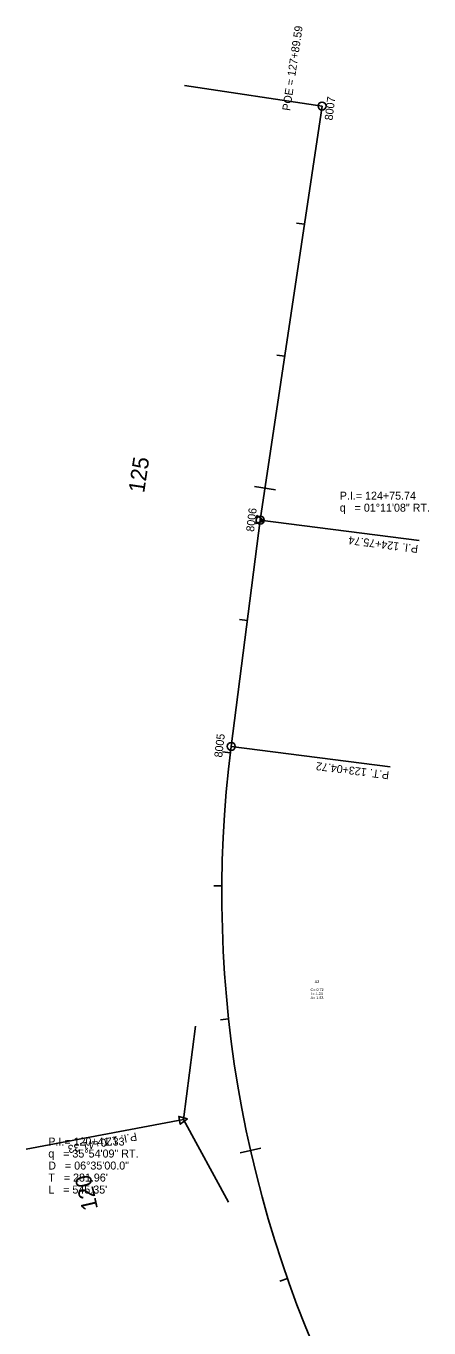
# Model space of a CAD drawing. Extents: x 1627557 to 1636561, y 783843 to 794002.
# Drawn here: x 1627557 to 1627859, y 785463 to 786439 of the extents above; entities that cross this region are included whole.
import ezdxf

# ---------------------------------------------------------------- set-up
doc = ezdxf.new("R2010")
doc.units = 0
for name, color, linetype in [('Point Numbers', 7, 'Continuous'), ('R_Drainage_Areas_Annot', 7, 'Continuous'), ('R_Horz Alg', 7, 'Continuous'), ('R_Horz Alg Annot', 7, 'Continuous')]:
    doc.layers.add(name, color=color, linetype=linetype)

msp = doc.modelspace()

# ---------------------------------------------------------------- linework, layer by layer
at = {"layer": 'R_Horz Alg'}
for p, q in [((1627732.9, 786068.26), (1627779.22, 786378.68)), ((1627711.17, 785898.63), (1627732.9, 786068.26))]:
    msp.add_line(p, q, dxfattribs=at)
for centre in [(1627779.22, 786378.68), (1627732.9, 786068.26), (1627711.17, 785898.63)]:
    msp.add_circle(centre, 3, dxfattribs=at)
msp.add_arc((1628574.42, 785788.02), 870.32, 172.69845, 208.60097, dxfattribs=at)
at = {"layer": 'R_Horz Alg Annot'}
for points in [[(1627779.22, 786378.68), (1627676.15, 786394.06)], [(1627760.06, 786290.95), (1627766, 786290.07)], [(1627745.31, 786192.05), (1627751.24, 786191.16)], [(1627728.57, 786093.44), (1627744.39, 786091.08)], [(1627732.9, 786068.26), (1627851.93, 786053.01)], [(1627717.32, 785993.9), (1627723.27, 785993.14)], [(1627711.17, 785898.63), (1627830.19, 785883.38)], [(1627704.62, 785894.68), (1627710.58, 785893.95)], [(1627698.13, 785794.25), (1627704.13, 785794.21)], [(1627703.19, 785693.75), (1627709.16, 785694.39)], [(1627709.07, 785557.06), (1627675.33, 785618.95), (1627684.29, 785688.87)], [(1627675.33, 785618.95), (1627557.4, 785596.78)], [(1627675.33, 785618.95), (1627557.4, 785596.78)], [(1627717.8, 785594.04), (1627733.4, 785597.58)], [(1627747.57, 785497.77), (1627753.23, 785499.76)]]:
    msp.add_lwpolyline(points, dxfattribs=at)
for points in [[(1627735.87, 786067.85), (1627729.52, 786065.71), (1627730.34, 786071.65)], [(1627678.28, 785619.51), (1627672.94, 785615.45), (1627671.83, 785621.35)]]:
    msp.add_lwpolyline(points, close=True, dxfattribs=at)

# ---------------------------------------------------------------- texts
at = {"layer": 'Point Numbers'}
for s, p in [('8007', (1627787.05, 786367.67)), ('8006', (1627728.2, 786059.31)), ('8005', (1627704.31, 785890.07))]:
    msp.add_text(s, height=6, rotation=83.28576, dxfattribs=at).set_placement(p)
at = {"layer": 'R_Drainage_Areas_Annot'}
for s, p in [('A2', (1627773.72, 785721.31)), ('C= 0.72', (1627770.59, 785715.31)), ('I= 4.24', (1627771.19, 785712.31)), ('A= 1.63', (1627770.62, 785709.31))]:
    msp.add_text(s, height=2, dxfattribs=at).set_placement(p)
at = {"layer": 'R_Horz Alg Annot'}
for s, height, rotation, p in [('POE = 127+89.59', 6, 81.44962, (1627755.24, 786374.81)), ('125', 12, 81.51298, (1627645.89, 786088.21)), ('P.I. 124+75.74', 6, 172.69845, (1627851.48, 786049.54)), ('P.T. 123+04.72', 6, 172.69845, (1627829.75, 785879.91)), ('P.I. 120+41.33', 6, 190.64971, (1627639.89, 785609.23)), ('P.I. 120+41.33', 6, 190.64971, (1627639.89, 785609.23)), ('120', 12, 102.75907, (1627611.4, 785552.22))]:
    msp.add_text(s, height=height, rotation=rotation, dxfattribs=at).set_placement(p)
for s, p in [('P.I.= 124+75.74', (1627792.45, 786083.59)), ('q   = 01%%d11\'08" RT.', (1627792.45, 786074.59)), ('P.I.= 120+41.33', (1627574.08, 785599.46)), ('q   = 35%%d54\'09" RT.', (1627574.08, 785590.46)), ('D   = 06%%d35\'00.0"', (1627574.08, 785581.46)), ("T   = 281.96'", (1627574.08, 785572.46)), ("L   = 545.35'", (1627574.08, 785563.46))]:
    msp.add_text(s, height=6, dxfattribs=at).set_placement(p)

doc.saveas('drawing.dxf')
